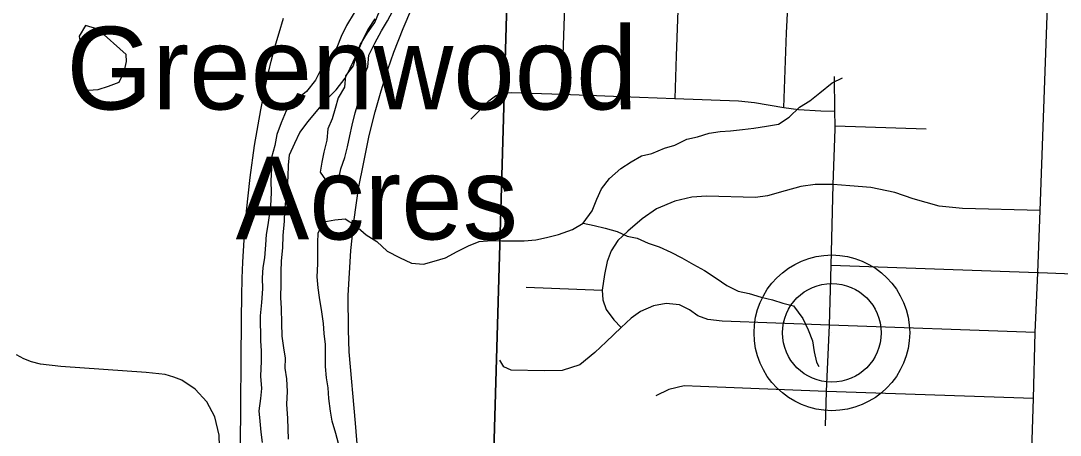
# Model space of a CAD drawing. Extents: x 0 to 34, y 0 to 22.
# Drawn here: x 3.672 to 4.666, y 15.431 to 15.827 of the extents above; entities that cross this region are included whole.
import ezdxf

# ---------------------------------------------------------------- set-up
doc = ezdxf.new("R2010")
doc.units = 0
for name, color, linetype in [('GM_X_Corporation', 7, 'Continuous'), ('GM_X_Major_River', 7, 'Continuous'), ('GM_X_Minor_Lake', 7, 'Continuous'), ('GM_X_Minor_River', 7, 'Continuous'), ('GM_X_Rail_Line', 7, 'Continuous'), ('GM_X_State_Route', 7, 'Continuous'), ('GM_X_Township_Road', 7, 'Continuous'), ('GM_X_Unincorporated', 7, 'Continuous'), ('GM_X_Unincorporated_Location', 7, 'Continuous'), ('GM_X_Unincorporated_Text', 7, 'Continuous')]:
    doc.layers.add(name, color=color, linetype=linetype)

msp = doc.modelspace()

# ---------------------------------------------------------------- linework, layer by layer
at = {"layer": 'GM_X_Corporation'}
for points in [[(3.11259, 15.99841), (4.14019, 15.96398), (4.11057, 14.94555), (3.0765, 14.98408)], [(4.14019, 15.96398), (5.1712, 15.93073), (5.12979, 14.91483), (4.11057, 14.94555)]]:
    msp.add_lwpolyline(points, close=True, dxfattribs=at)
at = {"layer": 'GM_X_Major_River'}
for points in [[(3.99063, 15.83458), (3.98348, 15.82278), (3.97822, 15.81213), (3.9741, 15.80149), (3.9677, 15.79198), (3.95978, 15.78246), (3.95377, 15.77029), (3.9451, 15.75963), (3.93452, 15.75086), (3.92584, 15.74095), (3.92097, 15.72955), (3.91685, 15.71852), (3.915, 15.70789), (3.91164, 15.69649), (3.91169, 15.68624), (3.91099, 15.67409), (3.91142, 15.66308), (3.91072, 15.65017), (3.90815, 15.63232), (3.90667, 15.62283), (3.90596, 15.61295), (3.90488, 15.6008), (3.9034, 15.59131), (3.90269, 15.58144), (3.90312, 15.57119), (3.90204, 15.5579), (3.90096, 15.54537), (3.90107, 15.52145), (3.90188, 15.51197), (3.90192, 15.5021), (3.90123, 15.48767), (3.90204, 15.47591), (3.90133, 15.46641), (3.89949, 15.45464), (3.90067, 15.44477), (3.90148, 15.43415), (3.90266, 15.42428)], [(3.92805, 15.42741), (3.9272, 15.44715), (3.92638, 15.46081), (3.92708, 15.47296), (3.92627, 15.48511), (3.9247, 15.49535), (3.92504, 15.50484), (3.92348, 15.5147), (3.92191, 15.52571), (3.92147, 15.53823), (3.92141, 15.55228), (3.9206, 15.5629), (3.92092, 15.57581), (3.92087, 15.5872), (3.9212, 15.59783), (3.92265, 15.61036), (3.92298, 15.62213), (3.92406, 15.6358), (3.92439, 15.64567), (3.92585, 15.6582), (3.92694, 15.66846), (3.92765, 15.67833), (3.92798, 15.68934), (3.92907, 15.69921), (3.93395, 15.71024), (3.93883, 15.7205), (3.94675, 15.73078), (3.95617, 15.74221), (3.96409, 15.75173), (3.97353, 15.76125), (3.9822, 15.77229), (3.98708, 15.7818), (3.99271, 15.79397), (3.99646, 15.80423), (4.00361, 15.81565), (4.01039, 15.82554), (4.01489, 15.83619)]]:
    msp.add_lwpolyline(points, dxfattribs=at)
at = {"layer": 'GM_X_Minor_Lake'}
for points in [[(3.74576, 15.81924), (3.73398, 15.82262), (3.72796, 15.81234), (3.72953, 15.8021), (3.72957, 15.79261), (3.72734, 15.78311), (3.72587, 15.77286), (3.72706, 15.76299), (3.73655, 15.76075), (3.74602, 15.76154), (3.75587, 15.76462), (3.76609, 15.76845), (3.77097, 15.77834), (3.7732, 15.78822), (3.77279, 15.79505)], [(3.77279, 15.79505), (3.74576, 15.81924)]]:
    msp.add_lwpolyline(points, dxfattribs=at)
at = {"layer": 'GM_X_Minor_River'}
for points in [[(4.01037, 15.82896), (4.00397, 15.81868), (3.99871, 15.80841), (3.99346, 15.79587), (3.98972, 15.78409), (3.98256, 15.77457), (3.98148, 15.76356), (3.97546, 15.75366), (3.97247, 15.74341), (3.96986, 15.73353), (3.96573, 15.72402), (3.96465, 15.71301), (3.96167, 15.70161), (3.95982, 15.69211), (3.95834, 15.68262), (3.9656, 15.67202), (3.97582, 15.67509), (3.97804, 15.68573), (3.98179, 15.69637), (3.98439, 15.70663), (3.98662, 15.71727), (3.98885, 15.72752), (3.99183, 15.7393), (3.99481, 15.74956), (3.99589, 15.76209), (3.99964, 15.77312), (4.00376, 15.783), (4.00484, 15.79439), (4.01048, 15.8058), (4.01687, 15.81759), (4.02251, 15.8271), (4.02778, 15.83661)], [(4.25557, 15.69245), (4.2654, 15.69818), (4.27525, 15.7005), (4.28736, 15.70548), (4.2972, 15.70817), (4.30893, 15.71391), (4.31916, 15.71622), (4.33014, 15.71968), (4.34075, 15.72124), (4.3506, 15.72203), (4.36197, 15.72322), (4.37296, 15.72439), (4.38509, 15.72634), (4.39645, 15.72828), (4.40666, 15.73515), (4.41647, 15.74468), (4.4263, 15.75079), (4.43613, 15.75841), (4.44783, 15.76795), (4.45767, 15.77254)], [(3.97584, 15.42341), (3.97314, 15.43289), (3.96968, 15.44465), (3.96812, 15.45413), (3.96654, 15.46627), (3.96574, 15.47652), (3.96418, 15.48601), (3.96337, 15.49701), (3.96328, 15.51789), (3.96209, 15.52851), (3.96129, 15.538), (3.95972, 15.549), (3.95776, 15.56266), (3.9562, 15.57214), (3.95539, 15.58239), (3.95609, 15.59492), (3.956, 15.61504), (3.95634, 15.62453), (3.9616, 15.63518), (3.9722, 15.63712), (3.98206, 15.63791), (3.99195, 15.63149), (4.00222, 15.6228), (4.01249, 15.61639), (4.02239, 15.60693), (4.03418, 15.60091), (4.04557, 15.59563), (4.05696, 15.59454), (4.06718, 15.59761), (4.07816, 15.60069), (4.08913, 15.6068), (4.1001, 15.61216), (4.11032, 15.61637), (4.12207, 15.61717), (4.13155, 15.61683), (4.15316, 15.61691), (4.16453, 15.61771), (4.17476, 15.62003), (4.18612, 15.62311), (4.19937, 15.62771), (4.20958, 15.63382), (4.21825, 15.64562), (4.22275, 15.65665), (4.22725, 15.66653), (4.23479, 15.67643), (4.24574, 15.68596), (4.25557, 15.69245)], [(4.20958, 15.63382), (4.22021, 15.63159), (4.23083, 15.62897), (4.24222, 15.62597), (4.25172, 15.62145), (4.26121, 15.61959), (4.27185, 15.6147), (4.28248, 15.61132), (4.2935, 15.60604), (4.30414, 15.60077), (4.31517, 15.59436), (4.32581, 15.5887), (4.33684, 15.58115), (4.34711, 15.57436), (4.35775, 15.5687), (4.36838, 15.56646), (4.37977, 15.56309), (4.39078, 15.56047), (4.40065, 15.55747), (4.4109, 15.55485), (4.41968, 15.54274), (4.42466, 15.53175), (4.42888, 15.52152), (4.43044, 15.51089), (4.43276, 15.50103), (4.43506, 15.49687)]]:
    msp.add_lwpolyline(points, dxfattribs=at)
at = {"layer": 'GM_X_Rail_Line'}
msp.add_lwpolyline([(3.88204, 15.4198), (3.88311, 15.54282), (3.8832, 15.56412), (3.8837, 15.58123), (3.88419, 15.5965), (3.88569, 15.61776), (3.88768, 15.64516), (3.89117, 15.67755), (3.89549, 15.70794), (3.90147, 15.74215), (3.90695, 15.76956), (3.91143, 15.78849), (3.91492, 15.80194), (3.9189, 15.81556), (3.92322, 15.82951)], dxfattribs=at)
at = {"layer": 'GM_X_State_Route'}
msp.add_lwpolyline([(3.99592, 15.39539), (3.99189, 15.44257), (3.98597, 15.51078), (3.98536, 15.53191), (3.98488, 15.56473), (3.98766, 15.60755), (3.99071, 15.63728), (3.99496, 15.66694), (4.00001, 15.69194), (4.00499, 15.7174), (4.01089, 15.74008), (4.01664, 15.76012), (4.02308, 15.78071), (4.02876, 15.79723), (4.03764, 15.81978), (4.04585, 15.83911)], dxfattribs=at)
at = {"layer": 'GM_X_Township_Road'}
for p, q in [((4.45066, 15.72674), (4.53761, 15.72376)), ((4.1552, 15.57268), (4.22786, 15.56976))]:
    msp.add_line(p, q, dxfattribs=at)
for points in [[(4.30038, 16.08384), (4.29501, 15.95879), (4.29673, 15.93999), (4.29944, 15.92549), (4.30228, 15.89827), (4.30161, 15.87199), (4.29849, 15.79371), (4.29727, 15.75281)], [(4.6309, 15.18985), (4.63185, 15.21155), (4.63377, 15.27985), (4.63827, 15.40694), (4.64027, 15.46626), (4.64194, 15.52918), (4.64431, 15.58623), (4.6465, 15.64581), (4.65524, 15.88547), (4.65705, 15.94382), (4.65974, 16.01803), (4.6616, 16.07173)], [(4.18946, 15.75707), (4.19603, 15.95312), (4.19759, 15.96118)], [(4.40156, 15.74428), (4.40413, 15.81552), (4.40526, 15.84026), (4.40345, 15.85777), (4.39587, 15.89041), (4.39411, 15.90382), (4.39492, 15.92333), (4.39614, 15.95576)], [(4.45055, 15.72368), (4.45066, 15.72674), (4.45032, 15.74089), (4.45014, 15.77395)], [(4.10224, 15.73324), (4.11951, 15.75057), (4.12581, 15.75552), (4.13265, 15.75829), (4.14084, 15.7587), (4.18946, 15.75707), (4.26341, 15.75416), (4.29727, 15.75281), (4.35822, 15.75064), (4.37339, 15.74915), (4.40156, 15.74428), (4.41564, 15.74252), (4.43691, 15.74116), (4.45032, 15.74089)], [(4.44154, 15.44025), (4.44222, 15.47296), (4.44506, 15.5365), (4.44695, 15.59336), (4.44869, 15.67073), (4.45055, 15.72368)], [(4.6465, 15.64581), (4.57248, 15.64781), (4.55, 15.65015), (4.52521, 15.65705), (4.50761, 15.66301), (4.48472, 15.66802), (4.46467, 15.66951), (4.44869, 15.67073), (4.43149, 15.6706), (4.41795, 15.66897), (4.40278, 15.66477), (4.38585, 15.6599), (4.37434, 15.65841), (4.32775, 15.65949), (4.31352, 15.65854), (4.29741, 15.65475), (4.27976, 15.64739), (4.26612, 15.63789), (4.25244, 15.62624), (4.24282, 15.6173), (4.23639, 15.60742), (4.23253, 15.59705), (4.23016, 15.58466), (4.22786, 15.56976), (4.22847, 15.56069), (4.23179, 15.55121), (4.2389, 15.54139), (4.24607, 15.53416)], [(4.6453, 15.58619), (4.64431, 15.58623), (4.44695, 15.59336)], [(5.16069, 15.57385), (5.02395, 15.57815), (4.90885, 15.58136), (4.90068, 15.57869), (4.86515, 15.57902), (4.72683, 15.58323), (4.6453, 15.58619)], [(4.64194, 15.52918), (4.44506, 15.5365), (4.34263, 15.54016), (4.32879, 15.54183), (4.31945, 15.54533), (4.31128, 15.551), (4.30194, 15.55584), (4.28893, 15.55717), (4.27709, 15.55467), (4.26458, 15.5495), (4.25557, 15.54316), (4.24607, 15.53416), (4.23156, 15.52031), (4.22084, 15.51019), (4.20654, 15.49847), (4.18969, 15.49313), (4.17235, 15.4928), (4.14083, 15.49346), (4.13399, 15.49663), (4.12999, 15.5028)], [(3.80158, 14.96537), (3.80868, 15.00857), (3.82032, 15.07399), (3.83658, 15.16419), (3.85107, 15.24017), (3.85811, 15.28676), (3.86055, 15.31737), (3.86163, 15.34988), (3.86217, 15.41029), (3.86163, 15.43141), (3.85757, 15.44875), (3.84999, 15.46311), (3.83888, 15.4753), (3.82588, 15.48369), (3.81823, 15.48681), (3.8099, 15.48911), (3.79175, 15.49101), (3.71021, 15.49697), (3.69071, 15.49913), (3.68218, 15.50137), (3.67493, 15.50428), (3.66802, 15.508)], [(4.64027, 15.46626), (4.44222, 15.47296), (4.32192, 15.4776), (4.30614, 15.47827), (4.29151, 15.47475), (4.27919, 15.46879)]]:
    msp.add_lwpolyline(points, dxfattribs=at)
at = {"layer": 'GM_X_Unincorporated'}
for radius in [0.0744, 0.04716]:
    msp.add_circle((4.44746, 15.52903), radius, dxfattribs=at)
at = {"layer": 'GM_X_Unincorporated_Location'}
msp.add_line((4.44746, 15.52903), (4.44746, 15.52903), dxfattribs=at)

# ---------------------------------------------------------------- texts
at = {"layer": 'GM_X_Unincorporated_Text'}
for s, p in [('Greenwood', (3.71573, 15.74244)), ('Acres', (3.8774, 15.61827))]:
    msp.add_text(s, height=0.078977, rotation=0.00001, dxfattribs=at).set_placement(p)

doc.saveas('drawing.dxf')
